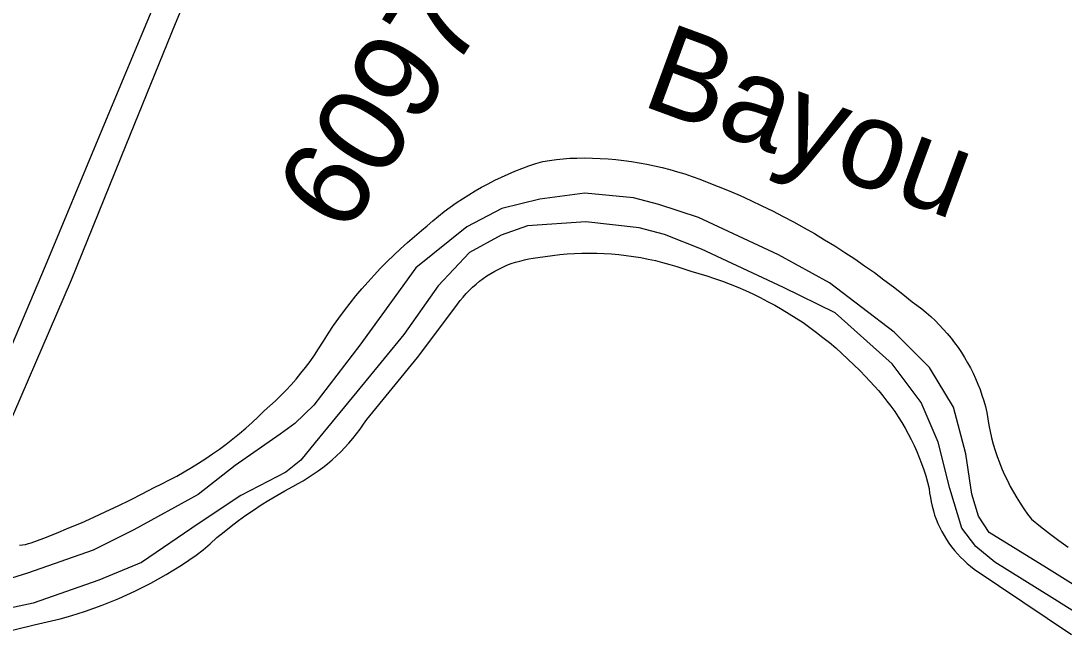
# Model space of a CAD drawing. Extents: x 3361039 to 3398939, y 576572 to 602007.
# Drawn here: x 3376248 to 3377434, y 584476 to 585190 of the extents above; entities that cross this region are included whole.
import ezdxf

# ---------------------------------------------------------------- set-up
doc = ezdxf.new("R2010")
doc.units = 0
for name, color, linetype in [('V-DTCH-CNTR', 7, 'Continuous'), ('V-RAIL-TRAK', 7, 'Continuous'), ('V-RIVR-IDEN', 7, 'Continuous'), ('V-SURV-IDEN', 7, 'Continuous'), ('V-TOPO-SHOR', 7, 'Continuous')]:
    doc.layers.add(name, color=color, linetype=linetype)

msp = doc.modelspace()

# ---------------------------------------------------------------- linework, layer by layer
at = {"layer": 'V-DTCH-CNTR'}
for points in [[(3376195.7, 584618.1), (3376194.5, 584621), (3376193.6, 584624), (3376192.8, 584627.1), (3376192.3, 584630.2), (3376191.9, 584633.3), (3376191.7, 584636.5), (3376191.8, 584639.7), (3376192, 584642.8), (3376192.4, 584645.9), (3376193.1, 584649), (3376193.9, 584652.1), (3376194.9, 584655.1), (3376196.1, 584658), (3376197.5, 584660.9), (3376199, 584663.6), (3376200.8, 584666.3), (3376240.1, 584744.8), (3376305.7, 584896.6), (3376367.9, 585049.8), (3376424, 585187.4), (3376458.6, 585270.2)], [(3376246.7, 584595.1), (3376250.1, 584595.5), (3376253.5, 584596.1), (3376256.8, 584596.9), (3376260.1, 584597.9), (3376274.5, 584603.3), (3376288.7, 584608.9), (3376302.9, 584614.7), (3376317.1, 584620.7), (3376331.1, 584626.9), (3376345, 584633.3), (3376358.9, 584639.9), (3376372.7, 584646.7), (3376386.3, 584653.6), (3376399.9, 584660.8), (3376408.5, 584664.9), (3376417.1, 584669.2), (3376425.5, 584673.7), (3376433.9, 584678.3), (3376442.1, 584683.2), (3376450.2, 584688.2), (3376458.3, 584693.4), (3376466.2, 584698.7), (3376474, 584704.3), (3376481.6, 584710), (3376489.2, 584715.9), (3376496.6, 584721.9), (3376503.9, 584728.1), (3376511, 584734.4), (3376518, 584740.9), (3376524.9, 584747.6), (3376531.3, 584753.2), (3376537.6, 584759), (3376543.7, 584765), (3376549.6, 584771.1), (3376555.4, 584777.3), (3376561, 584783.7), (3376566.5, 584790.3), (3376571.8, 584797), (3376576.9, 584803.8), (3376581.8, 584810.8), (3376586.5, 584817.9), (3376592.1, 584826.8), (3376597.8, 584835.7), (3376603.7, 584844.4), (3376609.8, 584853), (3376616.1, 584861.5), (3376622.5, 584869.9), (3376629.1, 584878.1), (3376635.8, 584886.2), (3376642.8, 584894.1), (3376649.9, 584901.9), (3376657.1, 584909.6), (3376664.5, 584917.1), (3376672, 584924.4), (3376679.7, 584931.6), (3376687.6, 584938.7), (3376695.6, 584945.6), (3376703.7, 584952.3), (3376710, 584957.9), (3376716.3, 584963.4), (3376722.9, 584968.8), (3376729.5, 584974), (3376736.3, 584979), (3376743.1, 584983.8), (3376750.1, 584988.5), (3376757.2, 584993), (3376764.5, 584997.4), (3376771.8, 585001.6), (3376779.2, 585005.5), (3376786.7, 585009.4), (3376794.3, 585013), (3376802, 585016.4), (3376809.8, 585019.7), (3376817.6, 585022.8), (3376825.5, 585025.7), (3376833.5, 585028.4), (3376841.5, 585030.8)], [(3376841.5, 585030.8), (3376849.2, 585032), (3376856.9, 585033), (3376864.6, 585033.8), (3376872.3, 585034.4), (3376880, 585034.7), (3376888.9, 585034.8), (3376897.8, 585034.6), (3376906.7, 585034.3), (3376915.6, 585033.7), (3376924.5, 585032.9), (3376933.4, 585031.9), (3376942.2, 585030.8), (3376951, 585029.3), (3376959.8, 585027.7), (3376968.5, 585025.9), (3376977.2, 585023.9), (3376985.8, 585021.7), (3376994.4, 585019.2), (3377002.9, 585016.6), (3377011.3, 585013.8), (3377019.7, 585010.7), (3377028, 585007.5), (3377040.6, 585002.5), (3377053.1, 584997.4), (3377065.6, 584992), (3377077.9, 584986.4), (3377090.2, 584980.6), (3377102.4, 584974.7), (3377114.4, 584968.5), (3377126.4, 584962.2), (3377138.3, 584955.6), (3377150, 584948.9), (3377161.7, 584942), (3377173.2, 584934.9), (3377184.6, 584927.6), (3377195.9, 584920.1), (3377207.1, 584912.5), (3377218.2, 584904.6), (3377229.1, 584896.6), (3377239.9, 584888.4), (3377250.6, 584880.1), (3377261.2, 584871.6), (3377266.6, 584867.6), (3377272, 584863.5), (3377277.2, 584859.2), (3377282.2, 584854.8), (3377287.2, 584850.2), (3377291.9, 584845.4), (3377296.5, 584840.5), (3377301, 584835.5), (3377305.3, 584830.2), (3377309.4, 584824.9), (3377313.4, 584819.5), (3377317.1, 584813.9), (3377320.7, 584808.2), (3377324.1, 584802.3), (3377327.3, 584796.4), (3377330.4, 584790.4), (3377333.2, 584784.3), (3377335.8, 584778.1), (3377338.3, 584771.8), (3377340.5, 584765.4), (3377342.5, 584759), (3377344.3, 584752.5), (3377345.9, 584745.9), (3377347, 584738.6), (3377348.2, 584731.4), (3377349.7, 584724.2), (3377351.4, 584717), (3377353.3, 584709.9), (3377355.4, 584702.8), (3377357.8, 584695.8), (3377360.4, 584688.9), (3377363.2, 584682), (3377366.2, 584675.2), (3377369.4, 584668.5), (3377372.7, 584661.9), (3377376.3, 584655.4), (3377380, 584649), (3377383.9, 584642.8), (3377388, 584636.6), (3377392.3, 584630.5), (3377396.7, 584624.6), (3377406.9, 584616.4), (3377417.3, 584608.4), (3377427.8, 584600.6), (3377438.4, 584592.9)], [(3376825.5, 584920.1), (3376830.6, 584921), (3376835.8, 584921.6), (3376844.1, 584923), (3376852.4, 584924.1), (3376860.7, 584925.1), (3376869.1, 584925.8), (3376877.5, 584926.4), (3376885.9, 584926.7), (3376894.3, 584926.8), (3376902.7, 584926.7), (3376911.2, 584926.3), (3376919.5, 584925.8), (3376927.9, 584925.1), (3376936.3, 584924.1), (3376944.6, 584922.9), (3376952.9, 584921.6), (3376961.2, 584920), (3376969.4, 584918.2), (3376977.6, 584916.2), (3376985.7, 584914), (3376993.7, 584911.5), (3377001.7, 584908.9), (3377009.7, 584906.1), (3377018.7, 584903.6), (3377027.7, 584900.9), (3377036.6, 584898), (3377045.5, 584894.8), (3377054.3, 584891.5), (3377063, 584888), (3377071.6, 584884.3), (3377080.1, 584880.4), (3377088.6, 584876.3), (3377096.9, 584872), (3377105.2, 584867.5), (3377113.3, 584862.8), (3377121.4, 584858), (3377129.3, 584853), (3377137.1, 584847.8), (3377144.8, 584842.4), (3377152.4, 584836.8), (3377159.8, 584831.1), (3377167.1, 584825.2), (3377174.3, 584819.1), (3377181.3, 584812.9), (3377188.2, 584806.5), (3377194.9, 584800), (3377201.5, 584793.3), (3377208, 584786.5), (3377213.2, 584781.2), (3377218.2, 584775.8), (3377223.2, 584770.3), (3377227.9, 584764.6), (3377232.5, 584758.8), (3377237, 584752.9), (3377241.3, 584746.9), (3377245.4, 584740.7), (3377249.3, 584734.4), (3377253.1, 584728), (3377256.6, 584721.6), (3377260.1, 584715), (3377263.3, 584708.3)], [(3376185.9, 584485.9), (3376263.3, 584504.9), (3376273.1, 584506.9), (3376283, 584509.2), (3376292.8, 584511.6), (3376302.5, 584514.3), (3376312.2, 584517.2), (3376321.8, 584520.3), (3376331.3, 584523.6), (3376340.8, 584527), (3376350.2, 584530.7), (3376359.5, 584534.6), (3376368.8, 584538.7), (3376377.9, 584543), (3376387, 584547.4), (3376395.9, 584552.1), (3376404.8, 584556.9), (3376413.5, 584562), (3376422.1, 584567.2), (3376430.7, 584572.6), (3376439.1, 584578.2), (3376447.4, 584583.9), (3376455.5, 584589.9), (3376463.3, 584596.8), (3376471.1, 584603.7), (3376479.2, 584610.3), (3376487.3, 584616.8), (3376495.7, 584623.1), (3376504.1, 584629.2), (3376512.7, 584635.1), (3376521.4, 584640.8), (3376530.2, 584646.4), (3376539.1, 584651.7), (3376548.1, 584656.9), (3376557.3, 584661.9), (3376563.3, 584665), (3376569.2, 584668.3), (3376574.9, 584671.9), (3376580.6, 584675.6), (3376586.1, 584679.4), (3376591.5, 584683.5), (3376596.8, 584687.7), (3376602, 584692), (3376607, 584696.6), (3376611.8, 584701.3), (3376616.5, 584706.1), (3376621.1, 584711.1), (3376625.5, 584716.2), (3376629.7, 584721.5), (3376633.8, 584726.8), (3376637.7, 584732.4), (3376641.4, 584738), (3376699, 584808.4), (3376741.6, 584864.5), (3376744.5, 584868.8), (3376747.6, 584872.9), (3376750.9, 584876.9), (3376754.3, 584880.8), (3376757.9, 584884.5), (3376761.6, 584888.1), (3376765.5, 584891.5), (3376769.5, 584894.8), (3376773.6, 584897.9), (3376777.9, 584900.9), (3376782.2, 584903.7), (3376786.7, 584906.2), (3376791.3, 584908.7), (3376796, 584910.9), (3376800.7, 584912.9), (3376805.6, 584914.8), (3376810.5, 584916.4), (3376815.4, 584917.8), (3376820.5, 584919.1), (3376825.5, 584920.1)], [(3377263.3, 584708.3), (3377266.3, 584701.6), (3377269.1, 584694.7), (3377271.8, 584687.8), (3377274.3, 584680.8), (3377276.5, 584673.8), (3377278.6, 584666.7), (3377280.5, 584659.5), (3377281, 584654.4), (3377281.8, 584649.3), (3377282.7, 584644.3), (3377283.8, 584639.3), (3377285.2, 584634.3), (3377286.7, 584629.4), (3377288.5, 584624.6), (3377290.4, 584619.8), (3377292.6, 584615.1), (3377294.9, 584610.6), (3377297.4, 584606.1), (3377300.1, 584601.7), (3377302.9, 584597.4), (3377306, 584593.3), (3377309.2, 584589.2), (3377312.5, 584585.3), (3377316, 584581.6), (3377319.7, 584578), (3377323.5, 584574.5), (3377327.4, 584571.2), (3377331.5, 584568.1), (3377442.4, 584493.9)]]:
    msp.add_lwpolyline(points, dxfattribs=at)
at = {"layer": 'V-RAIL-TRAK'}
msp.add_lwpolyline([(3376399.1, 585207.2), (3376337.8, 585060.4), (3376275.9, 584911.8), (3376185.6, 584700)], dxfattribs=at)
at = {"layer": 'V-TOPO-SHOR'}
for points in [[(3377508.7, 584510), (3377413.8, 584569.5), (3377348.8, 584609.7), (3377336.5, 584628.1), (3377328.8, 584653), (3377322, 584698.7), (3377308, 584751.7), (3377280.9, 584797), (3377240.7, 584837.1), (3377167.3, 584893.1), (3377109.4, 584924.9), (3377018.2, 584967.3), (3376973.3, 584982), (3376944.6, 584989.4), (3376889.1, 584995), (3376838.2, 584988.1), (3376795, 584977.3), (3376755, 584956.7), (3376697.2, 584910.1), (3376669.5, 584871.8), (3376633.3, 584822.4), (3376581.2, 584754.2), (3376559.5, 584733.5), (3376543.1, 584721.2), (3376491.9, 584685.6), (3376449.9, 584652.6), (3376376.5, 584612.6), (3376330.6, 584589.5), (3376256, 584563.2), (3376208.2, 584548.5)], [(3377515, 584476), (3377420.1, 584535.5), (3377355.1, 584575.7), (3377333.6, 584593.5), (3377317.5, 584614.5), (3377304.1, 584659.7), (3377290.7, 584712), (3377271.4, 584757.2), (3377238.4, 584801.2), (3377173.5, 584859.1), (3377115, 584887.6), (3377021.9, 584931.4), (3376979.6, 584948), (3376950.9, 584955.4), (3376890.2, 584962.3), (3376824.2, 584957.6), (3376794.1, 584947.3), (3376758.1, 584927.3), (3376722.5, 584889.7), (3376683.6, 584834.5), (3376638.8, 584779.9), (3376582.9, 584711.8)], [(3376582.9, 584711.8), (3376566.4, 584691.6), (3376549.3, 584678), (3376498.2, 584651.6), (3376451, 584620), (3376385.3, 584575.4), (3376336.9, 584555.5), (3376262.3, 584529.2), (3376196.2, 584515.3), (3376158.9, 584509.7), (3376139.3, 584498.7), (3376109.2, 584499.6)]]:
    msp.add_lwpolyline(points, dxfattribs=at)

# ---------------------------------------------------------------- texts
at = {"layer": 'V-RIVR-IDEN'}
msp.add_text('Bayou', height=100, rotation=339.7963, dxfattribs=at).set_placement((3376951.4, 585095.3))
at = {"layer": 'V-SURV-IDEN'}
for s, rotation, p in [('6093+12.0', 59.5177, (3376145.5, 585128.7)), ('6097+60.7', 56.9482, (3376617.1, 584945))]:
    msp.add_text(s, height=100, rotation=rotation, dxfattribs=at).set_placement(p)

doc.saveas('drawing.dxf')
